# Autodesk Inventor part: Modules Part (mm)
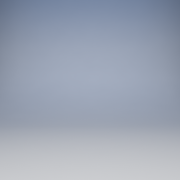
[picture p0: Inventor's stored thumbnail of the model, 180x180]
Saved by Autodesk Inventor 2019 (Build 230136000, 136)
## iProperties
Created: 2014-08
Part Number: Modules Part (mm)
Material: Generic
Document SubType Name: Modeling
Designer: Wally
Density: 1 g/cm^3
Appearance: Default
Author: Wally
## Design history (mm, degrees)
node "Sketch1"
